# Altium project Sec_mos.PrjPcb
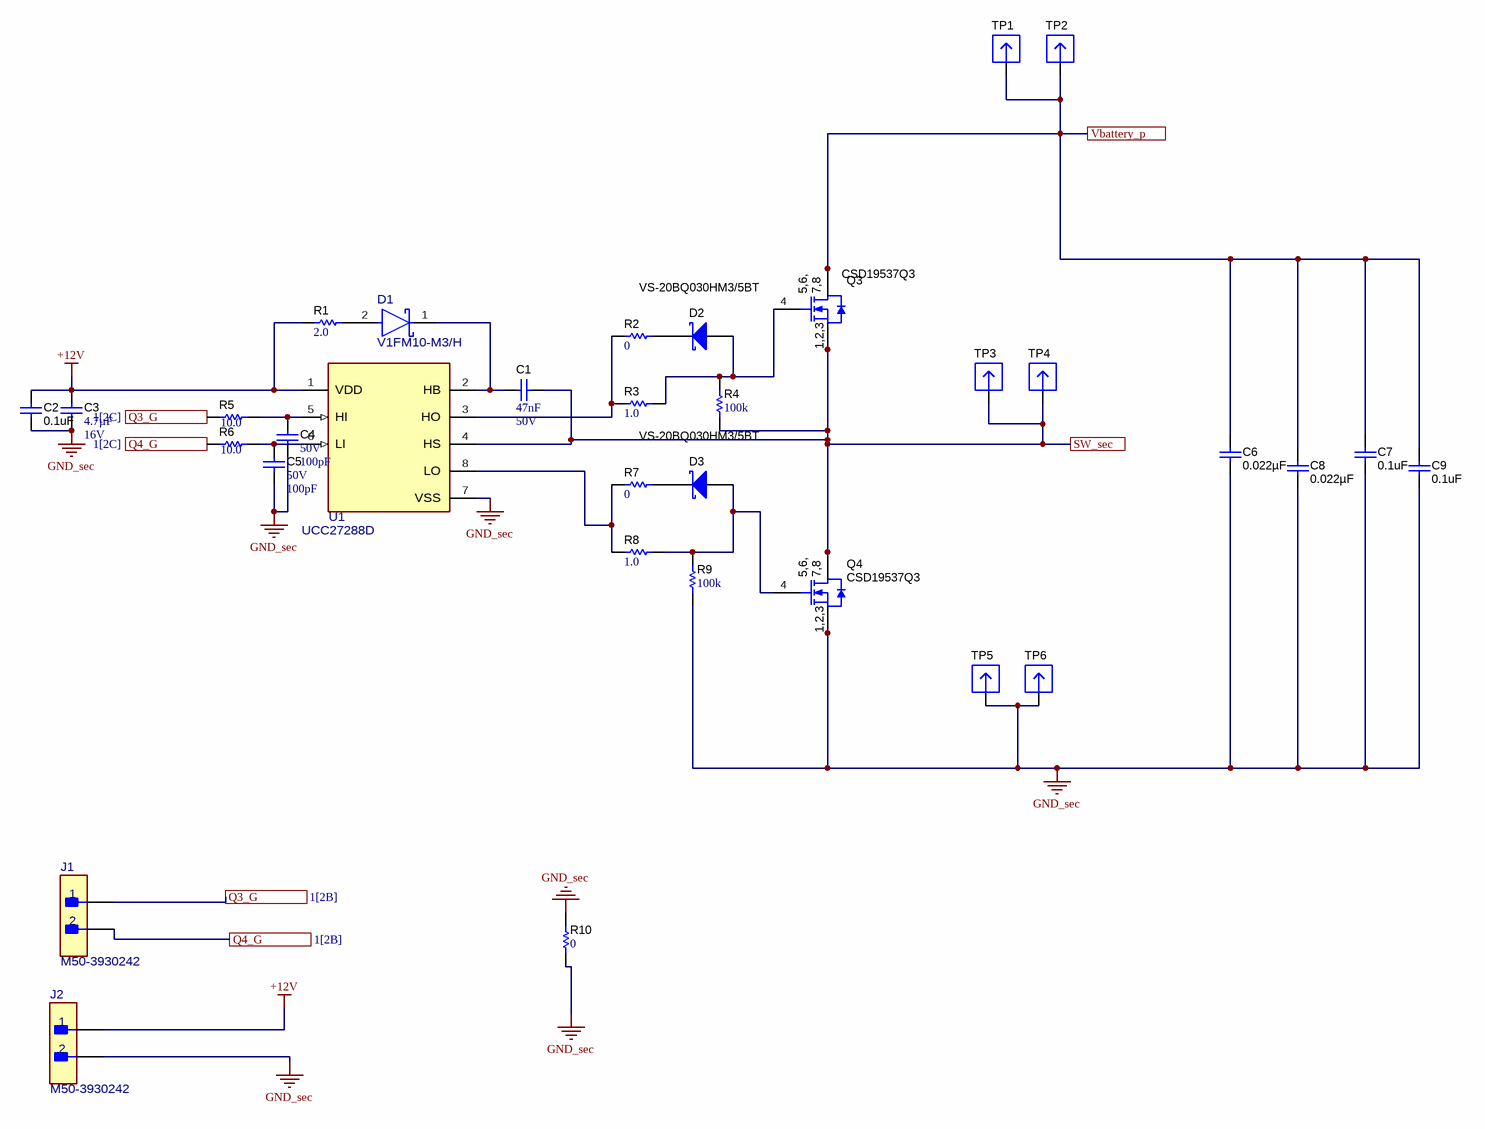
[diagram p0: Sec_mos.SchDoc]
1 sheet, 33 parts. Net scope: flat (ports and power ports of the same name join across sheets).
Board file: Sec_mos.PcbDoc

## Sheet Sec_mos.SchDoc
size 431 x 279 mm; Date: Not shown in title block; ApprovedBy: Not shown in title block; CheckedBy: Not shown in title block; Author: Not shown in title block; CompanyName: Not shown in title block; Engineer: Not shown in title block; Organization: Not shown in title block; Address1: Not shown in title block; Address2: Not shown in title block; Address3: Not shown in title block; Address4: Not shown in title block; DocumentNumber: 2; Revision: Use project parameter SCH_Rev; SheetNumber: 1; SheetTotal: 1; PageSetup: Record=PageOptions¦CenterHorizontal=True¦CenterVertical=True¦PrintScale=1.00¦XCorrection=1.00¦YCorrection=1.00¦PrintKind=0¦BorderSize=5000000¦LeftOffset=0¦BottomOffset=0¦Orientation=2¦PaperLength=1000¦PaperWidth=1000¦Scale=100¦PaperSource=15¦PrintQuality=600¦MediaType=1¦DitherType=10¦PaperKind=Letter¦PrintScaleMode=1

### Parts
C1  Cap_F: 47nF  VDC_V: 50V  [0805_HV]  (hidden comment: 08055C473JAT2A)
C2  ValueDisplayed: 0.1uF  [0402]  (hidden comment: 0402YC104KAT2A)
C3  Cap_F: 4.7µF  VDC_V: 16V  [0603]  (hidden comment: GRM188Z71C475KE21D)
C4  VDC_V: 50V  ValueDisplayed: 100pF  [0603]  (hidden comment: 06035A101FAT2A)
C5  VDC_V: 50V  ValueDisplayed: 100pF  [0603]  (hidden comment: 06035A101FAT2A)
C6  ValueDisplayed: 0.022µF  [1206_190]  (hidden comment: C1206C223KDRACTU)
C7  ValueDisplayed: 0.1uF  [1812_254]  (hidden comment: C1812W104KDRACTU)
C8  ValueDisplayed: 0.022µF  [1206_190]  (hidden comment: C1206C223KDRACTU)
C9  ValueDisplayed: 0.1uF  [1812_254]  (hidden comment: C1812W104KDRACTU)
D1  V1FM10-M3/H  [FP-V1FM10-M3-H_DO-219AB-MFG]
D2  VS-20BQ030HM3/5BT  [SMB]
D3  VS-20BQ030HM3/5BT  [SMB]
J1  M50-3930242  [FP-M50-3930242_HDR2-MFG]
J2  M50-3930242  [FP-M50-3930242_HDR2-MFG]
Q3  CSD19537Q3  [DQG0008A]
Q4  CSD19537Q3  [DQG0008A]
R1  ValueDisplayed: 2.0  [0805_HV]  (hidden comment: RC0805JR-072RL)
R2  ValueDisplayed: 0  [0805_HV]  (hidden comment: MCR10EZPJ000)
R3  ValueDisplayed: 1.0  [0805_HV]  (hidden comment: RC0805JR-071RL)
R4  ValueDisplayed: 100k  [0603]  (hidden comment: RT0603BRD07100KL)
R5  ValueDisplayed: 10.0  [0603]  (hidden comment: TNPW060310R0BEEA)
R6  ValueDisplayed: 10.0  [0603]  (hidden comment: TNPW060310R0BEEA)
R7  ValueDisplayed: 0  [0805_HV]  (hidden comment: MCR10EZPJ000)
R8  ValueDisplayed: 1.0  [0805_HV]  (hidden comment: RC0805JR-071RL)
R9  ValueDisplayed: 100k  [0603]  (hidden comment: RT0603BRD07100KL)
R10  ValueDisplayed: 0  [0805_HV]  (hidden comment: PMR10EZPJ000)
TP1  3621-0-32-15-00-00-08-0  [Mill-Max_3621-0-32-xx-00-00-08-0]  (value not drawn)
TP2  3621-0-32-15-00-00-08-0  [Mill-Max_3621-0-32-xx-00-00-08-0]  (value not drawn)
TP3  3621-0-32-15-00-00-08-0  [Mill-Max_3621-0-32-xx-00-00-08-0]  (value not drawn)
TP4  3621-0-32-15-00-00-08-0  [Mill-Max_3621-0-32-xx-00-00-08-0]  (value not drawn)
TP5  3621-0-32-15-00-00-08-0  [Mill-Max_3621-0-32-xx-00-00-08-0]  (value not drawn)
TP6  3621-0-32-15-00-00-08-0  [Mill-Max_3621-0-32-xx-00-00-08-0]  (value not drawn)
U1  UCC27288D  [D0008A-MFG]

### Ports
Q3_G (see 1[2B]), Q3_G (see 1[2C]), Q4_G (see 1[2B]), Q4_G (see 1[2C]), SW_sec, Vbattery_p

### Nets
+12V: C2.2 C3.2 J2.1 R1.1 U1.1(VDD)
GND_sec: C2.1 C3.1 C4.2 C5.2 C6.2 C7.2 C8.2 C9.2 J2.2 Q4.1(S) Q4.2(S) Q4.3(S) R9.1 R10.1 R10.2 TP5.1 TP6.1 U1.7(VSS)
NetC1_1: C1.1 Q3.1(S) Q3.2(S) Q3.3(S) Q4.5(D) Q4.6(D) Q4.7(D) Q4.8(D) Q4.9(D) R4.1 TP3.1 TP4.1 U1.4(HS) ; port SW_sec
NetC1_2: C1.2 D1.1(CATHODE) U1.2(HB)
NetC4_1: C4.1 R5.2 U1.5(HI)
NetC5_1: C5.1 R6.2 U1.6(LI)
NetC6_1: C6.1 C7.1 C8.1 C9.1 Q3.5(D) Q3.6(D) Q3.7(D) Q3.8(D) Q3.9(D) TP1.1 TP2.1 ; port Vbattery_p
NetD1_2: D1.2(ANODE) R1.2
NetD2_1: D2.1(K) R2.2
NetD2_2: D2.2(A) Q3.4(G) R3.2 R4.2
NetD3_1: D3.1(K) R7.2
NetD3_2: D3.2(A) Q4.4(G) R8.2 R9.2
NetJ1_1: J1.1 R5.1 ; port Q3_G
NetJ1_2: J1.2 R6.1 ; port Q4_G
NetR2_1: R2.1 R3.1 U1.3(HO)
NetR7_1: R7.1 R8.1 U1.8(LO)

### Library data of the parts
C1 = CMP-0007658-2: CAP, CERM, 0.047 uF, 50 V, +/- 5%, X7R, 0805; Manufacturer: AVX; TaMin_C: -55°C; ESR_ohm: 0.035; Polarized: N; SizeAreaWB_mm2: 6.75; Value1: 0.035 ohm; U/M: EA; TaMax_C: 125°C; SizeZ_mm: 1.45; SizeX_mm: 2; SizeY_mm: 1.25; Cap_Case: 0805; SizeArea_mm2: 2.5; AEC Category: Q200
C2 = CMP-0006201-2: CAP, CERM, 0.1 uF, 16 V, +/- 10%, X7R, 0402; Manufacturer: AVX; Polarized: N; Value: 0.1uF; U/M: EA; Cap_F: 100nF; Value1: Unknown; VDC_V: 16V; TaMin_C: -55°C; TaMax_C: 125°C; SizeArea_mm2: 0.5; SizeAreaWB_mm2: 3; SizeX_mm: 1; SizeZ_mm: 0.6; AEC Category: Q200
C3 = CMP-0064936-4: CAP, CERM, 4.7 uF, 16 V,+/- 10%, X7R, 0603; Manufacturer: MuRata; TaMin_C: -55°C; Polarized: N; SizeAreaWB_mm2: 4.68; Value1: Unknown; U/M: EA; Value: 4.7uF; TaMax_C: 125°C; SizeZ_mm: 1; SizeX_mm: 1.6; SizeY_mm: 0.8; SizeArea_mm2: 1.28; AEC Category: Q200
C4 C5 = CMP-0006762-4: CAP, CERM, 100 pF, 50 V, +/- 1%, C0G/NP0, 0603; Manufacturer: AVX; TaMin_C: -55°C; Polarized: N; SizeAreaWB_mm2: 4.68; Value1: Unknown; U/M: EA; TaMax_C: 125°C; SizeZ_mm: 1; SizeX_mm: 1.6; SizeY_mm: 0.8; SizeArea_mm2: 1.28; Value: 100pF; AEC Category: Q200
C6 C8 = CMP-0084048-1: CAP, CERM, 0.022 µF, 1000 V,+/- 10%, X7R, AEC-Q200 Grade 1, 1206; Manufacturer: Kemet; Polarized: N; CompType: Capacitor; Value: 0.022uF; U/M: EA; Cap_F: 22nF; VDC_V: 1kV; Value2: 1000V; TaMin_C: -55°C; TaMax_C: 125°C; Cap_Case: 1206; SizeArea_mm2: 5.12; SizeAreaWB_mm2: 10.92; SizeX_mm: 3.2; SizeY_mm: 1.6; SizeZ_mm: 1.9; AEC Category: Q200; AEC Qualified: Y; AEC Grade: 1
C7 C9 = CMP-0009326-2: CAP, CERM, 0.1 uF, 1000 V, +/- 10%, X7R, 1812; Manufacturer: Kemet; Polarized: N; Value: 0.1uF; U/M: EA; Cap_F: 100nF; Value1: Unknown; VDC_V: 1kV; Value2: 1000V; TaMin_C: -55°C; TaMax_C: 125°C; Cap_Case: 1812; AEC Category: Q200; SizeArea_mm2: 14.4; SizeAreaWB_mm2: 23.1; SizeX_mm: 4.5; SizeY_mm: 3.2; SizeZ_mm: 2.54
D1 = CMP-0093639-2: Diode Schottky 1A Surface Mount DO-219AB (SMF); Manufacturer: Vishay; Max Surge Forward Current: 30A; TJmax_C: 175°C; AEC Qualified: No; Cap_F: 95pF; AEC Category: Q101; Standoff Height: 0mm; SizeZ_mm: 1.08mm; Vr_V: 100V; Peak Reverse Current: 0.2uA
D2 D3 = CMP-0028909-2: Diode, Schottky, 30 V, 2 A, AEC-Q101, SMB; Manufacturer: Vishay-Semiconductor; Value1: 2A; Vf_V: 470mV; AEC Category: Q101; Green_Lifecycle: Not Set; SizeArea_mm2: 21.336; SizeZ_mm: 2.6; Value: 30V; Value2: 0.47V; SizeX_mm: 5.6; TJmax_C: 150°C; AEC Qualified: Y; Green_REACh: Incomplete; SizeAreaWB_mm2: 44.156; SizeY_mm: 3.81
J1 J2 = CMP-0097272-1: Conn Unshrouded HDR 2 POS 1.27mm Solder RA Through Hole Box; Manufacturer: Harwin; AEC Qualified: No; Row_Count: 1; Conn Gender: Male; Conn Orientation: Right Angle; SizeZ_mm: 2.3mm; Current_A: 1A; ContactFinish: Gold,Nickel
Q3 Q4 = CMP-0000967-2: MOSFET, N-CH, 100 V, 50 A, DQG0008A (VSON-CLIP-8); Alternate Manufacturer: None; Manufacturer: Texas Instruments; SizeZ_mm: 1.1; ChType: N; Value2: 16 nC; VdsMax_V: 100V; SizeX_mm: 3.3; Vgs_V: 20V; QgTyp_nC: 16; Value: 100V; SizeArea_mm2: 10.89; AEC Category: Q101; IdsMax_A: 50A; SizeAreaWB_mm2: 18.49; U/M: EA
R1 = CMP-0020815-2: RES, 2.0, 5%, 0.125 W, 0805; Manufacturer: Yageo America; Power_W: 125mW; TempCo: 200 ppm/C; Value_Code: 2R00; U/M: EA; Value: 2.0; EIA_Code: E24; Res_ohm: 2; SizeY_mm: 1.25; SizeZ_mm: 1.45; Value2: 0.125W; SizeArea_mm2: 2.5; VDC_V: 150V; AEC Category: Q200
R2 R7 = CMP-0020802-2: RES, 0, 5%, 0.125 W, 0805; Manufacturer: Rohm; Power_W: 125mW; TempCo: 400 ppm/C; Value_Code: 0000; U/M: EA; Value: 0; EIA_Code: E24; SizeX_mm: 2; SizeY_mm: 1.25; SizeZ_mm: 1.45; Value2: 0.125W; SizeArea_mm2: 2.5; VDC_V: 150V; AEC Category: Q200
R3 R8 = CMP-0020811-2: RES, 1.0, 5%, 0.125 W, 0805; Manufacturer: Yageo America; Power_W: 125mW; TempCo: 200 ppm/C; Value_Code: 1R00; U/M: EA; Value: 1.0; EIA_Code: E24; Res_ohm: 1; SizeX_mm: 2; SizeY_mm: 1.25; SizeZ_mm: 1.45; Value2: 0.125W; SizeArea_mm2: 2.5; VDC_V: 150V; AEC Category: Q200
R4 R9 = CMP-0023630-3: RES, 100 k, 0.1%, 0.1 W, 0603; Manufacturer: Yageo America; Power_W: 100mW; TempCo: 25 ppm/C; U/M: EA; Value: 100k; EIA_Code: E192; SizeX_mm: 1.6; SizeY_mm: 0.8; SizeZ_mm: 1; Value2: 0.1W; SizeArea_mm2: 1.28; VDC_V: 75V; AEC Category: Q200
R5 R6 = CMP-0025687-2: RES, 10.0, 0.1%, 0.1 W, 0603; Manufacturer: Vishay-Dale; Power_W: 100mW; TempCo: 25 ppm/C; Value_Code: 10R0; U/M: EA; Value: 10.0; EIA_Code: E192; Res_ohm: 10; SizeX_mm: 1.6; SizeY_mm: 0.8; SizeZ_mm: 1; Value2: 0.1W; SizeArea_mm2: 1.28; VDC_V: 75V; AEC Category: Q200
R10 = CMP-0081857-1: RES, 0, 0%,  W, AEC-Q200 Grade 0, 0805; Manufacturer: Rohm; SizeAreaWB_mm2: 6.75; SizeArea_mm2: 2.5; AEC Qualified: Y; AEC Category: Q200; Value: 0; SizeZ_mm: 1.45; SizeY_mm: 1.25; SizeX_mm: 2
TP1-TP6 = CMP-0082316-1: PCB Pin, 0.04" DIA, Edge-Mount; Manufacturer: Mill-Max; CompType: PCB Pin; ContactFinish: Gold; Gender: Male; Row_Count: 1
U1 = CMP-0088395-1: 120-V Boot, 3-A Peak, High-Frequency High-Side/Low-Side Driver; Manufacturer: Texas Instruments; TJmax_C: +140°C; Number Of Outputs: 1; AEC Qualified: No; Min Supply Voltage: 8V; Fall Time: 10ns; Standoff Height: 0.11mm; Propagation Delay: 13ns; Rise Time: 12ns; Nominal Supply Current: 2.2uA; SizeZ_mm: 1.75mm; Max Supply Voltage: 16V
